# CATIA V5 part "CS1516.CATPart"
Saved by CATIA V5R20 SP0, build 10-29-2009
Part number: CS1516
Revision: 5
Definition: design
Nomenclature: CS1516
Source: made
Description: NOT SPECIFIED
Bounding box of the stored display mesh (mm): x -15 to 15, y -15 to 15, z -28 to 7.5
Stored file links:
  C:\Users\Raffaele\Desktop\3D X SITO CF\BOLEX\20-TILTED COLUMN SUPPORT\CS1516.CATPart
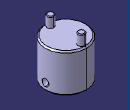
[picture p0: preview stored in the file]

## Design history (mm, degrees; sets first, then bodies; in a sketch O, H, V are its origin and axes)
Body1 "MANIFOLD_SOLID_BREP #691" (main body)
  Solid1: solid without history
